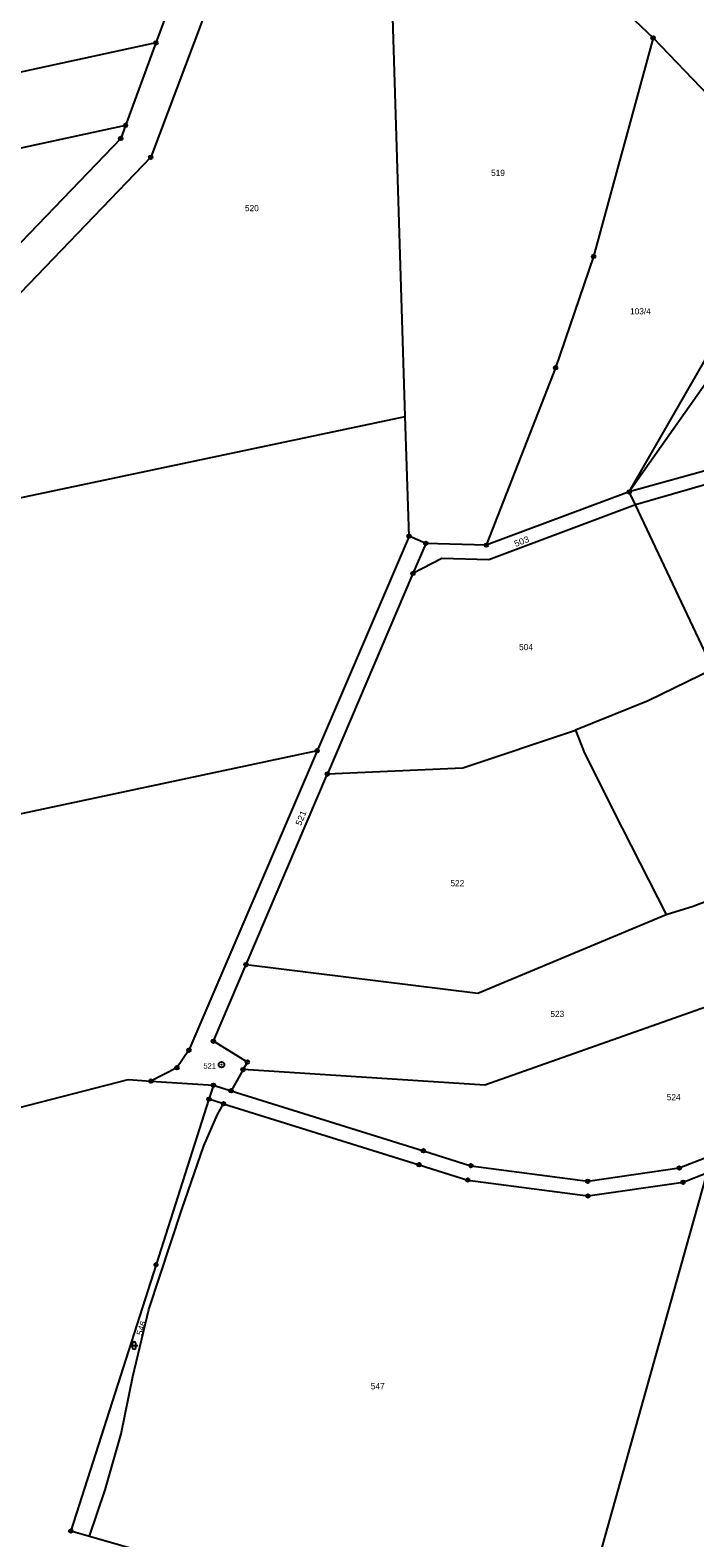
# Model space of a CAD drawing. Extents: x -719614 to -717765, y -1095834 to -1093862.
# Drawn here: x -719095.8 to -718913.7, y -1095578 to -1095165.2 of the extents above; entities that cross this region are included whole.
import ezdxf
from ezdxf.enums import TextEntityAlignment as Align

# ---------------------------------------------------------------- set-up
doc = ezdxf.new("R2010")
doc.units = 0
doc.header["$LTSCALE"] = 0.68
for name, color, linetype, lineweight in [('1', 7, 'Continuous', 25), ('3', 7, 'Continuous', 25), ('8', 7, 'Continuous', 25)]:
    doc.layers.add(name, color=color, linetype=linetype, lineweight=lineweight)
doc.layers.add('2', color=7, linetype='Continuous')

msp = doc.modelspace()

# ---------------------------------------------------------------- linework, layer by layer
at = {"layer": '1'}
for p, q in [((-719033.81, -1095123.24), (-719062.73, -1095199.98)), ((-718993, -1095270.99), (-718997.51, -1095125.46)), ((-719047.7, -1095131.78), (-719061.31, -1095168.69)), ((-718943.6, -1095149.69), (-718925.14, -1095167.33)), ((-718925.14, -1095167.33), (-718941.43, -1095227.14)), ((-718925.14, -1095167.33), (-718910.01, -1095182.96)), ((-719061.31, -1095168.69), (-719189.98, -1095196.44)), ((-719061.31, -1095168.69), (-719069.65, -1095191.3)), ((-719069.65, -1095191.3), (-719187.93, -1095216.84)), ((-719069.65, -1095191.3), (-719070.95, -1095194.83)), ((-719070.95, -1095194.83), (-719122.48, -1095248.36)), ((-719062.73, -1095199.98), (-719166.26, -1095307.55)), ((-718941.43, -1095227.14), (-718951.86, -1095257.64)), ((-718931.65, -1095291.63), (-718899.32, -1095235.26)), ((-718893.77, -1095237.74), (-718931.65, -1095291.63)), ((-718951.86, -1095257.64), (-718970.82, -1095306.22)), ((-719166.26, -1095307.55), (-718993, -1095270.99)), ((-718991.98, -1095303.75), (-718993, -1095270.99)), ((-718877.81, -1095276.75), (-718931.65, -1095291.63)), ((-718893.38, -1095284.58), (-718929.96, -1095295.21)), ((-718931.65, -1095291.63), (-718970.82, -1095306.22)), ((-718929.96, -1095295.21), (-718931.65, -1095291.63)), ((-718929.96, -1095295.21), (-718970.16, -1095310.24)), ((-718908.69, -1095340.19), (-718929.96, -1095295.21)), ((-718991.98, -1095303.75), (-719017.15, -1095362.51)), ((-718987.38, -1095305.72), (-718991.98, -1095303.75)), ((-718982.96, -1095309.86), (-718990.9, -1095313.98)), ((-718970.16, -1095310.24), (-718982.96, -1095309.86)), ((-718990.9, -1095313.98), (-719014.33, -1095368.86)), ((-718908.69, -1095340.19), (-718926.51, -1095348.86)), ((-718926.51, -1095348.86), (-718946.38, -1095356.9)), ((-718977.26, -1095367.21), (-718946.38, -1095356.9)), ((-718946.38, -1095356.9), (-718943.91, -1095363.18)), ((-719017.15, -1095362.51), (-719113.18, -1095382.94)), ((-719017.15, -1095362.51), (-719052.28, -1095444.52)), ((-718943.91, -1095363.18), (-718933.57, -1095383.71)), ((-719036.61, -1095421.06), (-719014.33, -1095368.86)), ((-719014.33, -1095368.86), (-718977.26, -1095367.21)), ((-718933.57, -1095383.71), (-718921.58, -1095407.39)), ((-718914.16, -1095405.09), (-718906.55, -1095402.14)), ((-718973.15, -1095428.87), (-718921.58, -1095407.39)), ((-718921.58, -1095407.39), (-718914.16, -1095405.09)), ((-719045.57, -1095442.06), (-719036.61, -1095421.06)), ((-719036.61, -1095421.06), (-718973.15, -1095428.87)), ((-718892.08, -1095426.15), (-718971.21, -1095454.09)), ((-719052.28, -1095444.52), (-719055.58, -1095449.32)), ((-719036.27, -1095447.78), (-719045.57, -1095442.06)), ((-719055.58, -1095449.32), (-719062.68, -1095452.97)), ((-719037.43, -1095449.83), (-719036.27, -1095447.78)), ((-719195.29, -1095484.97), (-719068.94, -1095452.55)), ((-719068.94, -1095452.55), (-719062.68, -1095452.97)), ((-719062.68, -1095452.97), (-719045.57, -1095454.11)), ((-719037.43, -1095449.83), (-719040.72, -1095455.62)), ((-718971.21, -1095454.09), (-719037.43, -1095449.83)), ((-719045.57, -1095454.11), (-719046.79, -1095457.92)), ((-719045.57, -1095454.11), (-719040.72, -1095455.62)), ((-719040.72, -1095455.62), (-718988.05, -1095472.05)), ((-719046.79, -1095457.92), (-719061.29, -1095503.24)), ((-719042.78, -1095459.17), (-719046.79, -1095457.92)), ((-719044.47, -1095462.08), (-719042.78, -1095459.17)), ((-719042.78, -1095459.17), (-718989.25, -1095475.87)), ((-719048.16, -1095470.68), (-719044.47, -1095462.08)), ((-718917.97, -1095476.77), (-718888.73, -1095465.23)), ((-719054.23, -1095488.17), (-719048.16, -1095470.68)), ((-718988.05, -1095472.05), (-718975.02, -1095476.14)), ((-718989.25, -1095475.87), (-718975.88, -1095480.06)), ((-718975.02, -1095476.14), (-718943.02, -1095480.39)), ((-718910.42, -1095478.1), (-718949.18, -1095616.11)), ((-718943.02, -1095480.39), (-718917.97, -1095476.77)), ((-718916.93, -1095480.67), (-718910.42, -1095478.1)), ((-718975.88, -1095480.06), (-718943, -1095484.43)), ((-718943, -1095484.43), (-718916.93, -1095480.67)), ((-719063.27, -1095515.56), (-719054.23, -1095488.17)), ((-719061.29, -1095503.24), (-719084.63, -1095576.17)), ((-719067.65, -1095533.85), (-719063.27, -1095515.56)), ((-719070.85, -1095549.54), (-719067.65, -1095533.85)), ((-719075.24, -1095564.87), (-719070.85, -1095549.54)), ((-719079.54, -1095577.62), (-719075.24, -1095564.87)), ((-719084.63, -1095576.17), (-719079.54, -1095577.62)), ((-719079.54, -1095577.62), (-718955.33, -1095612.98))]:
    msp.add_line(p, q, dxfattribs=at)
msp.add_lwpolyline([(-718970.82, -1095306.22), (-718987.38, -1095305.72), (-718990.9, -1095313.98)], dxfattribs=at)
at = {"layer": '3'}
for p, q in [((-719068.301, -1095525.391), (-719066.299, -1095525.391)), ((-719067.801, -1095524.891), (-719067.801, -1095525.892)), ((-719066.799, -1095525.892), (-719066.799, -1095524.891))]:
    msp.add_line(p, q, dxfattribs=at)
for centre, start, end in [((-719067.3, -1095524.8909), 0, 180), ((-719067.3, -1095525.8909), 180, 359.98789)]:
    msp.add_arc(centre, 0.5, start, end, dxfattribs=at)
at = {"layer": '8'}
for centre, radius in [((-719061.31, -1095168.6899), 0.5), ((-718925.14, -1095167.3299), 0.5), ((-718925.14, -1095167.3299), 0.0303), ((-719061.31, -1095168.6899), 0.0303), ((-719069.65, -1095191.2999), 0.5), ((-719069.65, -1095191.2999), 0.0303), ((-719070.95, -1095194.8299), 0.5), ((-719070.95, -1095194.8299), 0.0303), ((-719062.73, -1095199.9799), 0.5), ((-719062.73, -1095199.9799), 0.0303), ((-718941.43, -1095227.1399), 0.5), ((-718941.43, -1095227.1399), 0.0303), ((-718951.86, -1095257.6399), 0.5), ((-718951.86, -1095257.6399), 0.0303), ((-718931.65, -1095291.6299), 0.5), ((-718931.65, -1095291.6299), 0.0303), ((-718991.98, -1095303.7499), 0.5), ((-718991.98, -1095303.7499), 0.0303), ((-718987.38, -1095305.7199), 0.5), ((-718987.38, -1095305.7199), 0.0303), ((-718970.82, -1095306.2199), 0.5), ((-718970.82, -1095306.2199), 0.0303), ((-718990.9, -1095313.9799), 0.5), ((-718990.9, -1095313.9799), 0.0303), ((-719017.15, -1095362.5099), 0.5), ((-719017.15, -1095362.5099), 0.0303), ((-719014.33, -1095368.8599), 0.5), ((-719014.33, -1095368.8599), 0.0303), ((-719036.61, -1095421.0599), 0.5), ((-719036.61, -1095421.0599), 0.0303), ((-719052.28, -1095444.5199), 0.5), ((-719052.28, -1095444.5199), 0.0303), ((-719045.57, -1095442.0599), 0.5), ((-719045.57, -1095442.0599), 0.0303), ((-719055.58, -1095449.3199), 0.5), ((-719055.58, -1095449.3199), 0.0303), ((-719043.35, -1095448.4598), 0.75), ((-719043.35, -1095448.4598), 0.03), ((-719037.43, -1095449.8299), 0.5), ((-719036.27, -1095447.7799), 0.5), ((-719036.27, -1095447.7799), 0.0303), ((-719062.68, -1095452.9699), 0.5), ((-719062.68, -1095452.9699), 0.0303), ((-719037.43, -1095449.8299), 0.0303), ((-719046.79, -1095457.9199), 0.5), ((-719045.57, -1095454.1099), 0.5), ((-719045.57, -1095454.1099), 0.0303), ((-719040.72, -1095455.6199), 0.5), ((-719040.72, -1095455.6199), 0.0303), ((-719046.79, -1095457.9199), 0.0303), ((-719042.78, -1095459.1699), 0.5), ((-719042.78, -1095459.1699), 0.0303), ((-718988.05, -1095472.0499), 0.5), ((-718988.05, -1095472.0499), 0.0303), ((-718989.25, -1095475.8699), 0.5), ((-718989.25, -1095475.8699), 0.0303), ((-718975.02, -1095476.1399), 0.5), ((-718975.02, -1095476.1399), 0.0303), ((-718917.97, -1095476.7699), 0.5), ((-718917.97, -1095476.7699), 0.0303), ((-718975.88, -1095480.0599), 0.5), ((-718975.88, -1095480.0599), 0.0303), ((-718943.02, -1095480.3899), 0.5), ((-718943.02, -1095480.3899), 0.0303), ((-718916.93, -1095480.6699), 0.5), ((-718916.93, -1095480.6699), 0.0303), ((-718943, -1095484.4299), 0.5), ((-718943, -1095484.4299), 0.0303), ((-719061.29, -1095503.2399), 0.5), ((-719061.29, -1095503.2399), 0.0303), ((-719084.63, -1095576.1699), 0.5), ((-719084.63, -1095576.1699), 0.0303)]:
    msp.add_circle(centre, radius, dxfattribs=at)

# ---------------------------------------------------------------- texts
at = {"layer": '2'}
for s, p in [('519', (-718967.619, -1095205.122)), ('520', (-719035.039, -1095214.762)), ('103/4', (-718928.6, -1095243.025)), ('504', (-718959.939, -1095334.972)), ('522', (-718978.749, -1095399.642)), ('523', (-718951.379, -1095435.442)), ('524', (-718919.499, -1095458.242)), ('547', (-719000.559, -1095537.362))]:
    msp.add_text(s, height=1.7, dxfattribs=at).set_placement(p, align=Align.CENTER)
for s, rotation, width, p in [('503', 21, 1.1, (-718960.8546, -1095305.9778)), ('521', 68, 1.1, (-719020.8051, -1095381.2474)), ('546', 72, 1.05, (-719064.4961, -1095520.8817))]:
    msp.add_text(s, height=1.7, rotation=rotation, dxfattribs=dict(at, width=width)).set_placement(p, align=Align.CENTER)
at = {"layer": '8'}
msp.add_text('521', height=1.5, dxfattribs=at).set_placement((-719044.849, -1095449.577), align=Align.RIGHT)

doc.saveas('drawing.dxf')
